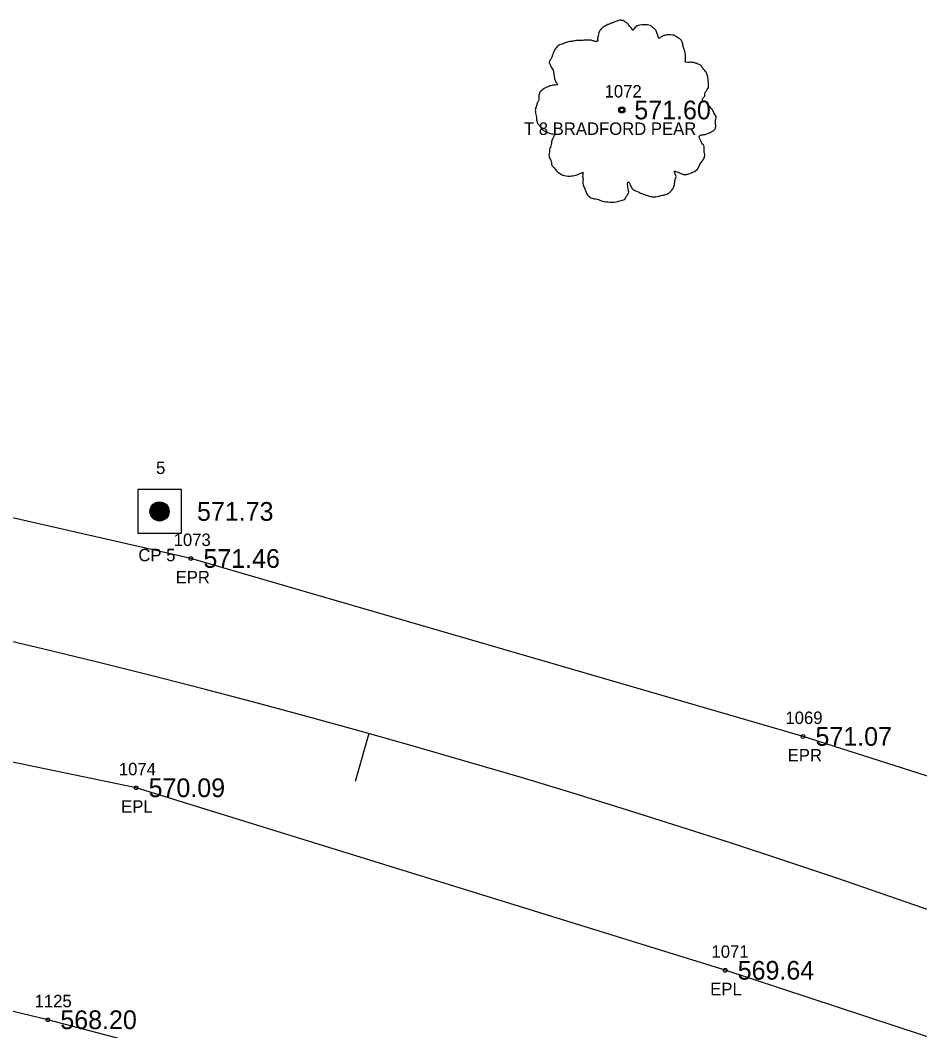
# Model space of a CAD drawing. Extents: x 1529475 to 1532053, y 876698 to 877911.
# Drawn here: x 1531319.5 to 1531391.7, y 877232.8 to 877313.9 of the extents above; entities that cross this region are included whole.
import ezdxf

# ---------------------------------------------------------------- set-up
doc = ezdxf.new("R2010")
doc.units = 0
for name, color, linetype in [('RD_EX_Fence_Other', 7, 'Continuous'), ('RD_EX_Fence_Other_txCode', 7, 'Continuous'), ('RD_EX_Road', 7, 'Continuous'), ('RD_EX_Road_txCode', 7, 'Continuous'), ('RD_EX_TX_Fence_Other_ELEV', 7, 'Continuous'), ('RD_EX_TX_Road_ELEV', 7, 'Continuous'), ('RD_EX_TX_VEG_ELEV', 7, 'Continuous'), ('RD_EX_VEG', 7, 'Continuous'), ('RD_EX_VEG_txCode', 7, 'Continuous'), ('RD_HC_Cl', 7, 'Continuous'), ('RD_HC_Data_Tic', 7, 'Continuous'), ('RD_HC_Survey', 7, 'Continuous'), ('RD_HC_Survey_ELEV', 7, 'Continuous'), ('RD_HC_Survey_txCode', 7, 'Continuous'), ('RD_SMD_Locator', 7, 'Continuous')]:
    doc.layers.add(name, color=color, linetype=linetype)

msp = doc.modelspace()

# ---------------------------------------------------------------- linework, layer by layer
at = {"layer": 'RD_EX_Fence_Other'}
msp.add_lwpolyline([(1531584.499, 877106.777), (1531547.822, 877137.371), (1531457.577, 877185.314), (1531406.019, 877209.641), (1531373.66, 877220.154), (1531357.948, 877224.144), (1531321.759, 877233.707), (1531272.233, 877245.587), (1531232.596, 877249.659), (1531180.727, 877254.109), (1531131.266, 877254.15), (1531075.59, 877251.89), (1531032.65, 877249.495), (1530920.264, 877239.274), (1530908.152, 877238.577)], dxfattribs=at)
at = {"layer": 'RD_EX_Road'}
for points in [[(1531606.641, 877133.837), (1531579.15, 877155.048), (1531564.866, 877165.268), (1531535.216, 877186.029), (1531511.532, 877200.27), (1531474.57, 877218.901), (1531430.451, 877239.347), (1531404.48, 877249.379), (1531382.323, 877256.431), (1531333.233, 877270.709), (1531303.666, 877277.444), (1531276.518, 877282.709), (1531237.324, 877287.202), (1531185.802, 877290.94), (1531132.609, 877292.767), (1531081.114, 877292.384), (1531038.69, 877288.667), (1530976.423, 877285.451), (1530941.057, 877284.256)], [(1531595.271, 877120.27), (1531553.556, 877149.901), (1531509.973, 877177.566), (1531465.943, 877201.729), (1531423.649, 877222.003), (1531376.086, 877237.675), (1531328.838, 877252.315), (1531282.814, 877261.847), (1531235.696, 877268.487), (1531185.47, 877272.841), (1531132.719, 877273.116), (1531080.205, 877271.871), (1531029.21, 877269.53), (1530978.473, 877268.316), (1530945.946, 877265.926), (1530941.447, 877262.437)]]:
    msp.add_lwpolyline(points, dxfattribs=at)
at = {"layer": 'RD_EX_VEG'}
for centre, radius in [((1531367.795, 877306.688), 0.25), ((1531367.782, 877306.669), 0.0001)]:
    msp.add_circle(centre, radius, dxfattribs=at)
for points in [[(1531367.926, 877313.855), (1531367.627, 877313.88), (1531367.302, 877313.78), (1531367.052, 877313.68), (1531366.827, 877313.605), (1531366.602, 877313.505), (1531366.302, 877313.33), (1531366.077, 877313.13), (1531365.952, 877312.88), (1531365.902, 877312.655), (1531365.852, 877312.381), (1531365.852, 877312.206), (1531365.727, 877312.181), (1531365.577, 877312.206), (1531365.328, 877312.281), (1531365.078, 877312.281), (1531364.828, 877312.281), (1531364.478, 877312.256), (1531364.128, 877312.256), (1531363.853, 877312.206), (1531363.528, 877312.156), (1531363.154, 877312.031), (1531362.804, 877311.906), (1531362.504, 877311.656), (1531362.254, 877311.181), (1531362.129, 877310.831), (1531361.979, 877310.581), (1531362.129, 877310.132), (1531362.304, 877309.782), (1531362.329, 877309.582), (1531362.404, 877309.157), (1531362.504, 877308.932), (1531362.629, 877308.732), (1531362.554, 877308.707), (1531362.179, 877308.657), (1531361.879, 877308.557), (1531361.454, 877308.332), (1531361.229, 877308.107), (1531361.129, 877307.783), (1531361.104, 877307.433), (1531361.005, 877307.233), (1531360.93, 877306.958), (1531360.905, 877306.883), (1531360.855, 877306.558), (1531360.955, 877306.108), (1531360.98, 877305.758), (1531361.104, 877305.534), (1531361.254, 877305.359), (1531361.429, 877305.109), (1531361.829, 877304.884), (1531362.154, 877304.784), (1531362.354, 877304.759), (1531362.179, 877304.259), (1531362.129, 877303.909), (1531362.004, 877303.509), (1531362.004, 877303.435), (1531361.954, 877302.96), (1531362.104, 877302.635), (1531362.179, 877302.26), (1531362.354, 877302.035), (1531362.629, 877301.735), (1531362.954, 877301.51), (1531363.453, 877301.385), (1531363.853, 877301.41), (1531364.428, 877301.585), (1531364.678, 877301.66), (1531364.653, 877301.485), (1531364.678, 877301.11), (1531364.678, 877300.686), (1531364.828, 877300.361), (1531364.928, 877300.086), (1531365.078, 877299.836), (1531365.403, 877299.611), (1531365.802, 877299.536), (1531366.227, 877299.386), (1531366.677, 877299.311), (1531367.177, 877299.286), (1531367.777, 877299.436), (1531368.051, 877299.561), (1531368.151, 877299.736), (1531368.351, 877300.111), (1531368.301, 877300.336), (1531368.326, 877300.936), (1531368.426, 877300.761), (1531368.601, 877300.411), (1531369.101, 877300.111), (1531369.501, 877299.936), (1531369.976, 877299.786), (1531370.275, 877299.711), (1531370.75, 877299.786), (1531371.125, 877299.861), (1531371.5, 877299.986), (1531371.8, 877300.261), (1531371.975, 877300.536), (1531372.025, 877300.811), (1531372.1, 877301.185), (1531372.15, 877301.36)], [(1531372.15, 877301.36), (1531372.075, 877301.535), (1531372.025, 877301.785), (1531372.1, 877301.76), (1531372.275, 877301.71), (1531372.549, 877301.585), (1531372.774, 877301.51), (1531373.099, 877301.535), (1531373.374, 877301.635), (1531373.824, 877301.91), (1531374.099, 877302.385), (1531374.374, 877302.785), (1531374.449, 877303.11), (1531374.399, 877303.335), (1531374.374, 877303.834), (1531374.174, 877304.084), (1531374.124, 877304.209), (1531374.024, 877304.609), (1531374.099, 877304.659), (1531374.374, 877304.709), (1531374.748, 877304.834), (1531375.023, 877304.959), (1531375.248, 877305.134), (1531375.323, 877305.359), (1531375.298, 877305.758), (1531375.348, 877306.158), (1531375.273, 877306.308), (1531375.173, 877306.458), (1531375.098, 877306.658), (1531374.948, 877306.808), (1531374.848, 877306.958), (1531374.748, 877307.058), (1531374.624, 877307.208), (1531374.449, 877307.333), (1531374.299, 877307.383), (1531374.249, 877307.533), (1531374.399, 877307.733), (1531374.449, 877307.833), (1531374.474, 877308.057), (1531374.699, 877308.407), (1531374.748, 877308.807), (1531374.699, 877309.232), (1531374.649, 877309.507), (1531374.499, 877309.782), (1531374.299, 877310.032), (1531374.174, 877310.207), (1531373.999, 877310.331), (1531373.674, 877310.456), (1531373.424, 877310.506), (1531373.074, 877310.506), (1531372.874, 877310.556), (1531372.899, 877310.606), (1531372.899, 877310.756), (1531372.899, 877311.031), (1531372.824, 877311.481), (1531372.674, 877311.981), (1531372.674, 877312.006), (1531372.574, 877312.256), (1531372.35, 877312.456), (1531372.175, 877312.555), (1531371.975, 877312.68), (1531371.725, 877312.705), (1531371.425, 877312.705), (1531371.15, 877312.655), (1531370.95, 877312.555), (1531370.775, 877312.431), (1531370.7, 877312.58), (1531370.6, 877312.88), (1531370.55, 877313.03), (1531370.4, 877313.205), (1531370.176, 877313.405), (1531369.726, 877313.53), (1531369.101, 877313.455), (1531368.801, 877313.255), (1531368.651, 877313.08), (1531368.601, 877313.205), (1531368.401, 877313.405), (1531368.301, 877313.58), (1531368.126, 877313.705), (1531367.976, 877313.805), (1531367.876, 877313.855)]]:
    msp.add_spline(points, degree=3, dxfattribs=at)
at = {"layer": 'RD_HC_Cl'}
msp.add_arc((1531152.265, 876558.444), 725, 47.423695, 92.332071, dxfattribs=at)
at = {"layer": 'RD_HC_Data_Tic'}
msp.add_line((1531347.495, 877256.664), (1531346.418, 877252.812), dxfattribs=at)
at = {"layer": 'RD_HC_Survey'}
for p, q in [((1531330.019, 877274.163), (1531330.019, 877274.807)), ((1531330.044, 877274.114), (1531330.044, 877274.856)), ((1531330.069, 877274.072), (1531330.069, 877274.898)), ((1531330.094, 877274.036), (1531330.094, 877274.935)), ((1531330.118, 877274.003), (1531330.118, 877274.967)), ((1531330.143, 877273.974), (1531330.143, 877274.996)), ((1531330.168, 877273.947), (1531330.168, 877275.023)), ((1531330.193, 877273.923), (1531330.193, 877275.047)), ((1531330.217, 877273.901), (1531330.217, 877275.069)), ((1531330.242, 877273.881), (1531330.242, 877275.09)), ((1531330.267, 877273.862), (1531330.267, 877275.108)), ((1531330.292, 877273.845), (1531330.292, 877275.126)), ((1531330.316, 877273.829), (1531330.316, 877275.141)), ((1531330.341, 877273.814), (1531330.341, 877275.156)), ((1531330.366, 877273.801), (1531330.366, 877275.169)), ((1531330.391, 877273.789), (1531330.391, 877275.181)), ((1531330.415, 877273.778), (1531330.415, 877275.193)), ((1531330.44, 877273.768), (1531330.44, 877275.203)), ((1531330.465, 877273.759), (1531330.465, 877275.212)), ((1531330.49, 877273.75), (1531330.49, 877275.22)), ((1531330.514, 877273.743), (1531330.514, 877275.227)), ((1531330.539, 877273.737), (1531330.539, 877275.234)), ((1531330.564, 877273.731), (1531330.564, 877275.239)), ((1531330.589, 877273.727), (1531330.589, 877275.244)), ((1531330.613, 877273.723), (1531330.613, 877275.247)), ((1531330.638, 877273.72), (1531330.638, 877275.25)), ((1531330.663, 877273.718), (1531330.663, 877275.253)), ((1531330.688, 877273.716), (1531330.688, 877275.254)), ((1531330.712, 877273.716), (1531330.712, 877275.255)), ((1531330.737, 877273.716), (1531330.737, 877275.254)), ((1531330.762, 877273.717), (1531330.762, 877275.253)), ((1531330.787, 877273.719), (1531330.787, 877275.252)), ((1531330.811, 877273.721), (1531330.811, 877275.249)), ((1531330.836, 877273.725), (1531330.836, 877275.246)), ((1531330.861, 877273.729), (1531330.861, 877275.241)), ((1531330.886, 877273.734), (1531330.886, 877275.236)), ((1531330.91, 877273.74), (1531330.91, 877275.23)), ((1531330.935, 877273.747), (1531330.935, 877275.223)), ((1531330.96, 877273.755), (1531330.96, 877275.216)), ((1531330.985, 877273.763), (1531330.985, 877275.207)), ((1531331.009, 877273.773), (1531331.009, 877275.197)), ((1531331.034, 877273.784), (1531331.034, 877275.187)), ((1531331.059, 877273.795), (1531331.059, 877275.175)), ((1531331.084, 877273.808), (1531331.084, 877275.162)), ((1531331.108, 877273.822), (1531331.108, 877275.148)), ((1531331.133, 877273.837), (1531331.133, 877275.133)), ((1531331.158, 877273.854), (1531331.158, 877275.117)), ((1531331.183, 877273.872), (1531331.183, 877275.099)), ((1531331.207, 877273.891), (1531331.207, 877275.079)), ((1531331.232, 877273.912), (1531331.232, 877275.058)), ((1531331.257, 877273.936), (1531331.257, 877275.035)), ((1531331.282, 877273.961), (1531331.282, 877275.009)), ((1531331.306, 877273.989), (1531331.306, 877274.981)), ((1531331.331, 877274.02), (1531331.331, 877274.951)), ((1531331.356, 877274.054), (1531331.356, 877274.916)), ((1531331.381, 877274.094), (1531331.381, 877274.877)), ((1531331.405, 877274.139), (1531331.405, 877274.832)), ((1531329.97, 877274.306), (1531329.97, 877274.664)), ((1531329.995, 877274.223), (1531329.995, 877274.747)), ((1531331.43, 877274.193), (1531331.43, 877274.777)), ((1531331.455, 877274.263), (1531331.455, 877274.708)), ((1531331.48, 877274.373), (1531331.48, 877274.597))]:
    msp.add_line(p, q, dxfattribs=at)
msp.add_lwpolyline([(1531332.468, 877276.235), (1531328.968, 877276.235), (1531328.968, 877272.735), (1531332.468, 877272.735)], close=True, dxfattribs=at)
msp.add_circle((1531330.718, 877274.485), 0.769, dxfattribs=at)
at = {"layer": 'RD_SMD_Locator'}
for centre in [(1531367.795, 877306.688), (1531330.718, 877274.485), (1531333.233, 877270.709), (1531382.323, 877256.431), (1531328.838, 877252.315), (1531376.086, 877237.675), (1531321.759, 877233.707)]:
    msp.add_circle(centre, 0.15, dxfattribs=at)

# ---------------------------------------------------------------- texts
at = {"layer": 'RD_EX_Fence_Other_txCode'}
msp.add_text('1125', height=1, dxfattribs=at).set_placement((1531320.696, 877234.707))
at = {"layer": 'RD_EX_Road_txCode'}
for s, p in [('1073', (1531331.847, 877271.709)), ('EPR', (1531332.004, 877268.709)), ('1069', (1531380.914, 877257.431)), ('EPR', (1531381.095, 877254.431)), ('1074', (1531327.452, 877253.315)), ('EPL', (1531327.634, 877250.315)), ('1071', (1531374.984, 877238.675)), ('EPL', (1531374.882, 877235.675))]:
    msp.add_text(s, height=1, dxfattribs=at).set_placement(p)
at = {"layer": 'RD_EX_TX_Fence_Other_ELEV'}
msp.add_text('568.20', height=1.5, dxfattribs=at).set_placement((1531322.759, 877232.957))
at = {"layer": 'RD_EX_TX_Road_ELEV'}
for s, p in [('571.46', (1531334.233, 877269.959)), ('571.07', (1531383.323, 877255.681)), ('570.09', (1531329.838, 877251.565)), ('569.64', (1531377.086, 877236.925))]:
    msp.add_text(s, height=1.5, dxfattribs=at).set_placement(p)
at = {"layer": 'RD_EX_TX_VEG_ELEV'}
msp.add_text('571.60', height=1.5, dxfattribs=at).set_placement((1531368.795, 877305.938))
at = {"layer": 'RD_EX_VEG_txCode'}
for s, p in [('1072', (1531366.409, 877307.688)), ('T 8 BRADFORD PEAR', (1531359.944, 877304.688))]:
    msp.add_text(s, height=1, dxfattribs=at).set_placement(p)
at = {"layer": 'RD_HC_Survey_ELEV'}
msp.add_text('571.73', height=1.5, dxfattribs=at).set_placement((1531333.718, 877273.735))
at = {"layer": 'RD_HC_Survey_txCode'}
for s, p in [('5', (1531330.435, 877277.485)), ('CP 5', (1531329.017, 877270.485))]:
    msp.add_text(s, height=1, dxfattribs=at).set_placement(p)

doc.saveas('drawing.dxf')
